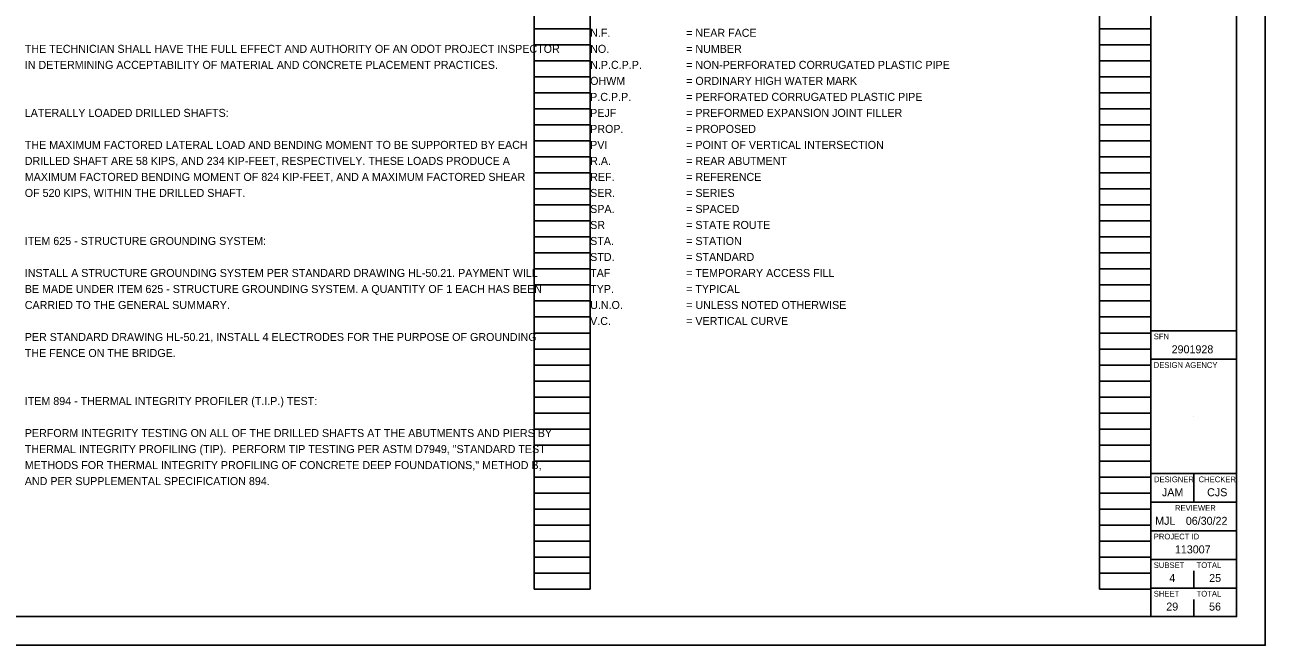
# Model space of a CAD drawing. Extents: x 0 to 34, y 0 to 22.
# Drawn here: x 12.29 to 34, y 0 to 10.85 of the extents above; entities that cross this region are included whole.
import ezdxf

# ---------------------------------------------------------------- set-up
doc = ezdxf.new("R2010")
doc.units = 0
for name, color, linetype in [('SH_Border', 7, 'Continuous'), ('SH_Cut_Line', 7, 'Continuous'), ('SH_Data', 7, 'Continuous'), ('SH_Text', 7, 'Continuous')]:
    doc.layers.add(name, color=color, linetype=linetype)

msp = doc.modelspace()

# ---------------------------------------------------------------- linework, layer by layer
at = {"layer": 'SH_Border'}
for p, q in [((32, 0.5), (32, 21.5)), ((32, 5.5), (33.5, 5.5)), ((32, 5), (33.5, 5)), ((32, 3), (33.5, 3)), ((32.75, 3), (32.75, 2.5)), ((32, 2.5), (33.5, 2.5)), ((32, 2), (33.5, 2)), ((32, 1.5), (33.5, 1.5)), ((32, 1), (33.5, 1))]:
    msp.add_line(p, q, dxfattribs=at)
msp.add_lwpolyline([(1.5, 21.5), (33.5, 21.5), (33.5, 0.5), (1.5, 0.5)], close=True, dxfattribs=at)
at = {"layer": 'SH_Cut_Line'}
msp.add_lwpolyline([(0, 0), (34, 0), (34, 22), (0, 22)], close=True, dxfattribs=at)
at = {"layer": 'SH_Data'}
for p, q in [((21.207, 0.98), (21.207, 21.14)), ((22.187, 0.98), (22.187, 21.14)), ((31.1, 0.98), (31.1, 21.14)), ((32, 0.98), (32, 21.14)), ((21.207, 10.78), (22.187, 10.78)), ((31.1, 10.78), (32, 10.78)), ((21.207, 10.5), (22.187, 10.5)), ((31.1, 10.5), (32, 10.5)), ((21.207, 10.22), (22.187, 10.22)), ((31.1, 10.22), (32, 10.22)), ((21.207, 9.94), (22.187, 9.94)), ((31.1, 9.94), (32, 9.94)), ((21.207, 9.66), (22.187, 9.66)), ((31.1, 9.66), (32, 9.66)), ((21.207, 9.38), (22.187, 9.38)), ((31.1, 9.38), (32, 9.38)), ((21.207, 9.1), (22.187, 9.1)), ((31.1, 9.1), (32, 9.1)), ((21.207, 8.82), (22.187, 8.82)), ((31.1, 8.82), (32, 8.82)), ((21.207, 8.54), (22.187, 8.54)), ((31.1, 8.54), (32, 8.54)), ((21.207, 8.26), (22.187, 8.26)), ((31.1, 8.26), (32, 8.26)), ((21.207, 7.98), (22.187, 7.98)), ((31.1, 7.98), (32, 7.98)), ((21.207, 7.7), (22.187, 7.7)), ((31.1, 7.7), (32, 7.7)), ((21.207, 7.42), (22.187, 7.42)), ((31.1, 7.42), (32, 7.42)), ((21.207, 7.14), (22.187, 7.14)), ((31.1, 7.14), (32, 7.14)), ((21.207, 6.86), (22.187, 6.86)), ((31.1, 6.86), (32, 6.86)), ((21.207, 6.58), (22.187, 6.58)), ((31.1, 6.58), (32, 6.58)), ((21.207, 6.3), (22.187, 6.3)), ((31.1, 6.3), (32, 6.3)), ((21.207, 6.02), (22.187, 6.02)), ((31.1, 6.02), (32, 6.02)), ((21.207, 5.74), (22.187, 5.74)), ((31.1, 5.74), (32, 5.74)), ((21.207, 5.46), (22.187, 5.46)), ((31.1, 5.46), (32, 5.46)), ((21.207, 5.18), (22.187, 5.18)), ((31.1, 5.18), (32, 5.18)), ((21.207, 4.9), (22.187, 4.9)), ((31.1, 4.9), (32, 4.9)), ((21.207, 4.62), (22.187, 4.62)), ((31.1, 4.62), (32, 4.62)), ((21.207, 4.34), (22.187, 4.34)), ((31.1, 4.34), (32, 4.34)), ((21.207, 4.06), (22.187, 4.06)), ((31.1, 4.06), (32, 4.06)), ((32.75, 4), (32.75, 4)), ((21.207, 3.78), (22.187, 3.78)), ((31.1, 3.78), (32, 3.78)), ((21.207, 3.5), (22.187, 3.5)), ((31.1, 3.5), (32, 3.5)), ((21.207, 3.22), (22.187, 3.22)), ((31.1, 3.22), (32, 3.22)), ((21.207, 2.94), (22.187, 2.94)), ((31.1, 2.94), (32, 2.94)), ((21.207, 2.66), (22.187, 2.66)), ((31.1, 2.66), (32, 2.66)), ((21.207, 2.38), (22.187, 2.38)), ((31.1, 2.38), (32, 2.38)), ((21.207, 2.1), (22.187, 2.1)), ((31.1, 2.1), (32, 2.1)), ((21.207, 1.82), (22.187, 1.82)), ((31.1, 1.82), (32, 1.82)), ((21.207, 1.54), (22.187, 1.54)), ((31.1, 1.54), (32, 1.54)), ((21.207, 1.26), (22.187, 1.26)), ((31.1, 1.26), (32, 1.26)), ((32.75, 1), (32.75, 1.3)), ((21.207, 0.98), (22.187, 0.98)), ((31.1, 0.98), (32, 0.98)), ((32.375, 0.675), (32.375, 0.675)), ((32.75, 0.5), (32.75, 0.8))]:
    msp.add_line(p, q, dxfattribs=at)

# ---------------------------------------------------------------- texts
for s, height, p in [('SFN', 0.1, (32.05, 5.35)), ('2901928', 0.14, (32.363, 5.105)), ('DESIGN AGENCY', 0.1, (32.05, 4.85)), ('DESIGNER', 0.1, (32.054, 2.85)), ('CHECKER', 0.1, (32.835, 2.85)), ('JAM', 0.14, (32.193, 2.605)), ('CJS', 0.14, (32.984, 2.605)), ('REVIEWER', 0.1, (32.422, 2.35)), ('MJL', 0.14, (32.075, 2.105)), ('06/30/22', 0.14, (32.611, 2.105)), ('PROJECT ID', 0.1, (32.05, 1.85)), ('113007', 0.14, (32.42, 1.605)), ('SUBSET', 0.1, (32.05, 1.35)), ('TOTAL', 0.1, (32.8, 1.35)), ('4', 0.14, (32.322, 1.105)), ('25', 0.14, (33.02, 1.105)), ('SHEET', 0.1, (32.05, 0.85)), ('TOTAL', 0.1, (32.8, 0.85)), ('29', 0.14, (32.269, 0.605)), ('56', 0.14, (33.018, 0.605))]:
    msp.add_text(s, height=height, dxfattribs=at).set_placement(p)
at = {"layer": 'SH_Text'}
for s, p in [('N.F.', (22.187, 10.64)), ('= NEAR FACE', (23.867, 10.64)), ('THE TECHNICIAN SHALL HAVE THE FULL EFFECT AND AUTHORITY OF AN ODOT PROJECT INSPECTOR ', (12.293, 10.36)), ('NO.', (22.187, 10.36)), ('= NUMBER', (23.867, 10.36)), ('IN DETERMINING ACCEPTABILITY OF MATERIAL AND CONCRETE PLACEMENT PRACTICES.', (12.293, 10.08)), ('N.P.C.P.P.', (22.187, 10.08)), ('= NON-PERFORATED CORRUGATED PLASTIC PIPE', (23.867, 10.08)), ('OHWM', (22.187, 9.8)), ('= ORDINARY HIGH WATER MARK', (23.867, 9.8)), ('P.C.P.P.', (22.187, 9.52)), ('= PERFORATED CORRUGATED PLASTIC PIPE', (23.867, 9.52)), ('LATERALLY LOADED DRILLED SHAFTS:', (12.293, 9.24)), ('PEJF', (22.187, 9.24)), ('= PREFORMED EXPANSION JOINT FILLER', (23.867, 9.24)), ('PROP.', (22.187, 8.96)), ('= PROPOSED', (23.867, 8.96)), ('THE MAXIMUM FACTORED LATERAL LOAD AND BENDING MOMENT TO BE SUPPORTED BY EACH ', (12.293, 8.68)), ('PVI', (22.187, 8.68)), ('= POINT OF VERTICAL INTERSECTION', (23.867, 8.68)), ('DRILLED SHAFT ARE 58 KIPS, AND 234 KIP-FEET, RESPECTIVELY. THESE LOADS PRODUCE A ', (12.293, 8.4)), ('R.A.', (22.187, 8.4)), ('= REAR ABUTMENT', (23.867, 8.4)), ('MAXIMUM FACTORED BENDING MOMENT OF 824 KIP-FEET, AND A MAXIMUM FACTORED SHEAR ', (12.293, 8.12)), ('REF.', (22.187, 8.12)), ('= REFERENCE', (23.867, 8.12)), ('OF 520 KIPS, WITHIN THE DRILLED SHAFT.', (12.293, 7.84)), ('SER.', (22.187, 7.84)), ('= SERIES', (23.867, 7.84)), ('SPA.', (22.187, 7.56)), ('= SPACED', (23.867, 7.56)), ('SR', (22.187, 7.28)), ('= STATE ROUTE', (23.867, 7.28)), ('ITEM 625 - STRUCTURE GROUNDING SYSTEM:', (12.293, 7)), ('STA.', (22.187, 7)), ('= STATION', (23.867, 7)), ('STD.', (22.187, 6.72)), ('= STANDARD', (23.867, 6.72)), ('INSTALL A STRUCTURE GROUNDING SYSTEM PER STANDARD DRAWING HL-50.21. PAYMENT WILL ', (12.293, 6.44)), ('TAF', (22.187, 6.44)), ('= TEMPORARY ACCESS FILL', (23.867, 6.44)), ('BE MADE UNDER ITEM 625 - STRUCTURE GROUNDING SYSTEM. A QUANTITY OF 1 EACH HAS BEEN ', (12.293, 6.16)), ('TYP.', (22.187, 6.16)), ('= TYPICAL', (23.867, 6.16)), ('CARRIED TO THE GENERAL SUMMARY.', (12.293, 5.88)), ('U.N.O.', (22.187, 5.88)), ('= UNLESS NOTED OTHERWISE', (23.867, 5.88)), ('V.C.', (22.187, 5.6)), ('= VERTICAL CURVE', (23.867, 5.6)), ('PER STANDARD DRAWING HL-50.21, INSTALL 4 ELECTRODES FOR THE PURPOSE OF GROUNDING ', (12.293, 5.32)), ('THE FENCE ON THE BRIDGE.', (12.293, 5.04)), ('ITEM 894 - THERMAL INTEGRITY PROFILER (T.I.P.) TEST:', (12.293, 4.2)), ('PERFORM INTEGRITY TESTING ON ALL OF THE DRILLED SHAFTS AT THE ABUTMENTS AND PIERS BY ', (12.293, 3.64)), ('THERMAL INTEGRITY PROFILING (TIP).  PERFORM TIP TESTING PER ASTM D7949, "STANDARD TEST ', (12.293, 3.36)), ('METHODS FOR THERMAL INTEGRITY PROFILING OF CONCRETE DEEP FOUNDATIONS," METHOD B, ', (12.293, 3.08)), ('AND PER SUPPLEMENTAL SPECIFICATION 894.', (12.293, 2.8))]:
    msp.add_text(s, height=0.14, dxfattribs=at).set_placement(p)

doc.saveas('drawing.dxf')
